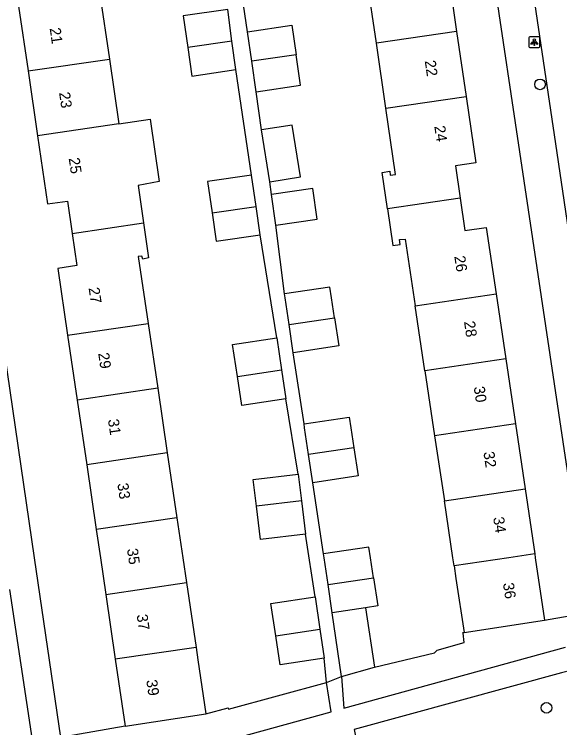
# Model space of a CAD drawing. Extents: x 159053 to 160041, y 380450 to 381422.
# Drawn here: x 159397.1 to 159447, y 380984.4 to 381049.8 of the extents above; entities that cross this region are included whole.
import ezdxf

# ---------------------------------------------------------------- set-up
doc = ezdxf.new("R2010")
doc.units = 0
for name, color, linetype in [('IMGEO_Boom', 7, 'Continuous'), ('IMGEO_Groenvoorziening', 7, 'Continuous'), ('IMGEO_Lichtpunt', 7, 'Continuous'), ('IMGEO_Pand', 7, 'Continuous'), ('IMGEO_Pand_nummerreeks', 7, 'Continuous'), ('IMGEO_Rijbaan_lokaal_open', 7, 'Continuous'), ('IMGEO_Voetpad_open', 7, 'Continuous')]:
    doc.layers.add(name, color=color, linetype=linetype)

msp = doc.modelspace()

# ---------------------------------------------------------------- linework, layer by layer
at = {"layer": 'IMGEO_Boom'}
for centre in [(159445.214, 381043.35), (159445.808, 380986.252)]:
    msp.add_circle(centre, 0.489, dxfattribs=at)
at = {"layer": 'IMGEO_Groenvoorziening'}
for points in [[(159445.63, 380994.272), (159449.622, 380994.989)], [(159430.044, 380989.966), (159435.538, 380991.287), (159435.788, 380991.543), (159438.272, 380992.234), (159438.16, 380993.08), (159438.151, 380993.149), (159438.257, 380993.165)], [(159414.62, 380985.695), (159416.659, 380986.246), (159416.684, 380986.131), (159425.664, 380988.567)], [(159407.214, 380984.584), (159401.289, 380983.538)]]:
    msp.add_lwpolyline(points, dxfattribs=at)
at = {"layer": 'IMGEO_Lichtpunt'}
for p, q in [((159444.193, 381047.619), (159444.193, 381046.812)), ((159444.193, 381047.619), (159444.193, 381046.812)), ((159445.095, 381047.714), (159444.287, 381047.714)), ((159445.095, 381047.714), (159444.287, 381047.714)), ((159445.189, 381046.812), (159445.189, 381047.619)), ((159445.189, 381046.812), (159445.189, 381047.619)), ((159444.287, 381046.718), (159445.095, 381046.718)), ((159444.287, 381046.718), (159445.095, 381046.718))]:
    msp.add_line(p, q, dxfattribs=at)
for points in [[(159444.567, 381047.283), (159444.606, 381047.255), (159444.418, 381046.993), (159444.38, 381047.02), (159444.567, 381047.283)], [(159444.669, 381047.235), (159444.716, 381047.235), (159444.716, 381046.913), (159444.669, 381046.913), (159444.669, 381047.235)], [(159444.779, 381047.255), (159444.817, 381047.282), (159445.004, 381047.02), (159444.965, 381046.992), (159444.779, 381047.255)]]:
    msp.add_lwpolyline(points, dxfattribs=at)
msp.add_circle((159444.692, 381047.417), 0.0994, dxfattribs=at)
for centre, start, end in [((159444.287, 381047.619), 90, 180), ((159444.287, 381047.619), 90, 180), ((159445.095, 381047.619), 0, 90), ((159445.095, 381047.619), 0, 90), ((159444.287, 381046.812), 180, 270), ((159444.287, 381046.812), 180, 270), ((159445.095, 381046.812), 270, 0), ((159445.095, 381046.812), 270, 360)]:
    msp.add_arc(centre, 0.0946, start, end, dxfattribs=at)
at = {"layer": 'IMGEO_Pand'}
for points in [[(159436.695, 381054.163), (159437.567, 381048.206)], [(159430.229, 381047.133), (159429.357, 381053.09)], [(159404.902, 381051.602), (159405.771, 381045.666)], [(159397.458, 381050.512), (159398.327, 381044.576)], [(159416.611, 381050.223), (159412.52, 381049.624), (159412.946, 381046.717)], [(159416.998, 381047.31), (159416.611, 381050.223)], [(159418.426, 381048.166), (159422.483, 381048.759), (159422.878, 381046.058)], [(159418.821, 381045.465), (159418.426, 381048.166)], [(159437.567, 381048.206), (159430.229, 381047.133)], [(159437.567, 381048.206), (159438.439, 381042.249)], [(159416.998, 381047.31), (159412.946, 381046.717)], [(159417.344, 381044.7), (159416.998, 381047.31)], [(159431.101, 381041.176), (159430.229, 381047.133)], [(159412.946, 381046.717), (159413.327, 381044.112), (159417.344, 381044.7)], [(159398.327, 381044.576), (159405.771, 381045.666)], [(159405.771, 381045.666), (159406.639, 381039.729)], [(159422.878, 381046.058), (159418.821, 381045.465)], [(159419.23, 381042.675), (159423.287, 381043.268), (159422.878, 381046.058)], [(159419.23, 381042.675), (159418.821, 381045.465)], [(159398.327, 381044.576), (159399.195, 381038.639)], [(159431.101, 381041.176), (159438.439, 381042.249)], [(159438.439, 381042.249), (159439.327, 381036.178), (159437.465, 381035.905), (159437.899, 381032.935)], [(159431.248, 381031.961), (159430.76, 381035.295), (159431.45, 381035.396), (159431.501, 381035.041), (159431.989, 381035.104), (159431.101, 381041.176)], [(159406.639, 381039.729), (159399.195, 381038.639)], [(159406.639, 381039.729), (159409.507, 381040.149), (159410.339, 381034.469), (159408.4, 381034.081), (159408.9, 381030.661)], [(159420.466, 381034.428), (159423.271, 381034.874), (159422.515, 381039.625), (159419.71, 381039.179)], [(159420.466, 381034.428), (159419.71, 381039.179)], [(159399.195, 381038.639), (159400.109, 381032.395), (159401.936, 381032.662), (159402.368, 381029.705)], [(159418.79, 381035.036), (159414.764, 381034.447), (159415.183, 381031.581)], [(159419.209, 381032.17), (159418.79, 381035.036)], [(159421.028, 381030.459), (159424.807, 381031.012), (159424.396, 381033.818), (159420.618, 381033.265)], [(159421.028, 381030.459), (159420.618, 381033.265)], [(159437.899, 381032.935), (159431.248, 381031.961)], [(159437.899, 381032.935), (159438.333, 381029.965), (159440.276, 381030.249), (159441.181, 381024.168)], [(159415.183, 381031.581), (159419.209, 381032.17)], [(159419.588, 381029.579), (159419.209, 381032.17)], [(159431.248, 381031.961), (159431.741, 381028.592), (159432.411, 381028.69), (159432.346, 381029.138), (159432.859, 381029.164), (159433.773, 381023.066)], [(159415.183, 381031.581), (159415.562, 381028.99), (159419.588, 381029.579)], [(159402.368, 381029.705), (159408.9, 381030.661)], [(159408.9, 381030.661), (159409.369, 381027.456), (159408.849, 381027.352), (159408.761, 381027.632), (159408.415, 381027.574), (159409.319, 381021.463)], [(159402.368, 381029.705), (159402.8, 381026.752), (159401.055, 381026.497), (159401.954, 381020.38)], [(159426.387, 381021.967), (159426.108, 381023.814), (159425.961, 381024.786), (159421.816, 381024.179)], [(159422.232, 381021.349), (159421.87, 381023.814), (159421.816, 381024.179)], [(159433.773, 381023.066), (159441.181, 381024.168)], [(159441.181, 381024.168), (159442.067, 381018.214)], [(159434.666, 381017.113), (159433.773, 381023.066)], [(159422.232, 381021.349), (159426.387, 381021.967)], [(159426.387, 381021.967), (159426.775, 381019.401), (159422.61, 381018.776)], [(159401.954, 381020.38), (159409.319, 381021.463)], [(159409.319, 381021.463), (159410.197, 381015.527)], [(159422.61, 381018.776), (159422.232, 381021.349)], [(159401.954, 381020.38), (159402.826, 381014.444)], [(159417.496, 381016.599), (159417.054, 381019.542), (159421.099, 381020.149)], [(159421.099, 381020.149), (159421.543, 381017.194)], [(159442.067, 381018.214), (159434.666, 381017.113)], [(159442.067, 381018.214), (159442.953, 381012.26)], [(159417.496, 381016.599), (159421.543, 381017.194)], [(159421.543, 381017.194), (159421.94, 381014.546)], [(159434.666, 381017.113), (159435.559, 381011.159)], [(159421.94, 381014.546), (159417.895, 381013.939), (159417.496, 381016.599)], [(159410.197, 381015.527), (159402.826, 381014.444)], [(159410.197, 381015.527), (159411.075, 381009.592)], [(159402.826, 381014.444), (159403.699, 381008.508)], [(159423.602, 381012.272), (159427.747, 381012.879), (159427.894, 381011.907), (159428.173, 381010.059)], [(159424.018, 381009.441), (159423.656, 381011.907), (159423.602, 381012.272)], [(159442.953, 381012.26), (159435.559, 381011.159)], [(159442.953, 381012.26), (159443.84, 381006.305)], [(159435.559, 381011.159), (159436.451, 381005.205)], [(159411.075, 381009.592), (159403.699, 381008.508)], [(159411.075, 381009.592), (159411.953, 381003.656)], [(159428.173, 381010.059), (159424.018, 381009.441)], [(159428.173, 381010.059), (159428.561, 381007.494), (159424.396, 381006.869)], [(159424.396, 381006.869), (159424.018, 381009.441)], [(159403.699, 381008.508), (159404.571, 381002.571)], [(159419.246, 381004.728), (159418.956, 381007.171), (159423.074, 381007.659)], [(159423.074, 381007.659), (159423.363, 381005.216)], [(159436.451, 381005.205), (159443.84, 381006.305)], [(159443.84, 381006.305), (159444.726, 381000.351)], [(159423.363, 381005.216), (159419.246, 381004.728)], [(159423.363, 381005.216), (159423.727, 381002.15)], [(159437.344, 380999.252), (159437.232, 381000), (159436.451, 381005.205)], [(159423.727, 381002.15), (159419.609, 381001.662), (159419.246, 381004.728)], [(159411.953, 381003.656), (159404.571, 381002.571)], [(159411.953, 381003.656), (159412.494, 381000), (159412.831, 380997.721)], [(159404.571, 381002.571), (159404.949, 381000), (159405.443, 380996.635)], [(159429.958, 380998.152), (159429.679, 381000), (159429.532, 381000.972), (159425.387, 381000.365)], [(159425.803, 380997.533), (159425.441, 381000), (159425.387, 381000.365)], [(159444.726, 381000.351), (159442.366, 381000), (159437.344, 380999.252)], [(159444.726, 381000.351), (159444.778, 381000), (159445.63, 380994.272)], [(159437.344, 380999.252), (159437.515, 380998.11), (159438.257, 380993.165)], [(159425.803, 380997.533), (159429.958, 380998.152)], [(159429.958, 380998.152), (159430.346, 380995.587), (159429.242, 380995.421)], [(159405.443, 380996.635), (159412.831, 380997.721)], [(159412.831, 380997.721), (159413.709, 380991.786)], [(159426.181, 380994.962), (159425.803, 380997.533)], [(159405.443, 380996.635), (159406.316, 380990.699)], [(159421.008, 380992.859), (159420.566, 380995.801), (159424.611, 380996.408)], [(159424.611, 380996.408), (159425.054, 380993.454)], [(159429.242, 380995.421), (159426.181, 380994.962)], [(159429.242, 380995.421), (159430.044, 380989.966)], [(159427.041, 380989.114), (159426.181, 380994.962)], [(159438.257, 380993.165), (159445.63, 380994.272)], [(159421.008, 380992.859), (159425.054, 380993.454)], [(159425.054, 380993.454), (159425.452, 380990.805)], [(159425.452, 380990.805), (159421.407, 380990.198), (159421.008, 380992.859)], [(159413.709, 380991.786), (159406.316, 380990.699)], [(159413.709, 380991.786), (159413.878, 380990.64), (159414.62, 380985.695)], [(159406.316, 380990.699), (159407.214, 380984.584)], [(159427.041, 380989.114), (159430.044, 380989.966)], [(159407.214, 380984.584), (159414.62, 380985.695)]]:
    msp.add_lwpolyline(points, dxfattribs=at)
at = {"layer": 'IMGEO_Rijbaan_lokaal_open'}
for points in [[(159451.207, 381006.916), (159447.686, 381030.883), (159446.657, 381037.89), (159443.858, 381056.823)], [(159399.423, 380978.652), (159398.743, 380983.277), (159396.672, 380997.098)]]:
    msp.add_lwpolyline(points, dxfattribs=at)
at = {"layer": 'IMGEO_Voetpad_open'}
for points in [[(159435.479, 381089.722), (159448.874, 381000), (159449.622, 380994.989)], [(159386.52, 381084.815), (159398.888, 381000), (159401.289, 380983.538)], [(159418.426, 381048.166), (159417.949, 381051.477), (159417.076, 381057.378), (159416.597, 381060.621), (159415.744, 381066.501)], [(159418.79, 381035.036), (159417.344, 381044.7)], [(159419.71, 381039.179), (159419.23, 381042.675)], [(159420.618, 381033.265), (159420.466, 381034.428)], [(159421.816, 381024.179), (159421.028, 381030.459)], [(159421.099, 381020.149), (159419.588, 381029.579)], [(159423.602, 381012.272), (159422.61, 381018.776)], [(159423.074, 381007.659), (159421.94, 381014.546)], [(159425.387, 381000.365), (159424.396, 381006.869)], [(159424.611, 380996.408), (159423.727, 381002.15)], [(159427.041, 380989.114), (159427.248, 380986.213), (159447.546, 380991.822)], [(159425.664, 380988.567), (159425.452, 380990.805)], [(159449.011, 380983.736), (159448.118, 380989.715), (159447.176, 380989.466), (159428.187, 380984.259), (159429.341, 380978.394)], [(159425.664, 380988.567), (159427.041, 380989.114)], [(159405.022, 380980.072), (159426.077, 380985.889), (159425.664, 380988.567)]]:
    msp.add_lwpolyline(points, dxfattribs=at)

# ---------------------------------------------------------------- texts
at = {"layer": 'IMGEO_Pand_nummerreeks'}
for s, rotation, p in [('21', 278.32489, (159400.302, 381048.478)), ('22', 278.3243, (159434.649, 381045.497)), ('23', 278.32489, (159401.164, 381042.585)), ('24', 278.3243, (159435.524, 381039.512)), ('25', 278.32487, (159402.044, 381036.58)), ('26', 278.46527, (159437.356, 381027.594)), ('27', 278.36012, (159403.867, 381024.694)), ('28', 278.46527, (159438.246, 381021.612)), ('29', 278.36012, (159404.745, 381018.722)), ('30', 278.46527, (159439.135, 381015.632)), ('31', 278.36012, (159405.638, 381012.639)), ('32', 278.46527, (159440.024, 381009.658)), ('33', 278.36012, (159406.5, 381006.777)), ('34', 278.46527, (159440.915, 381003.676)), ('35', 278.35699, (159407.381, 381000.787)), ('36', 278.4606, (159441.812, 380997.647)), ('37', 278.35867, (159408.266, 380994.761)), ('39', 278.35867, (159409.147, 380988.765))]:
    msp.add_text(s, height=1, rotation=rotation, dxfattribs=at).set_placement(p)

doc.saveas('drawing.dxf')
